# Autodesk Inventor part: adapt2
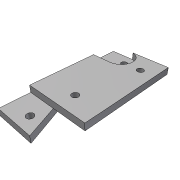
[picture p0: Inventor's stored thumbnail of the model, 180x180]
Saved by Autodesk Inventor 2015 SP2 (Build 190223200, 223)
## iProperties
Created: 2016-02
Part Number: adapt2
Material: S235JR (E24-2)
Document SubType Name: Modeling
Designer: BreysseC
Density: 7.85 g/cm^3
Appearance: Acier
Author: BreysseC
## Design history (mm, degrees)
sketch "Esquisse3"
  geometry: L1 (-26.5, 55)-(26.5, 55); L2 (26.5, 55)-(26.5, -55); L3 (26.5, -55)-(-26.5, -55); L4 (-26.5, -55)-(-26.5, 55); L5 (-37.1, 0)-(37.1, 0) reference; L6 (0, -77)-(0, 77) reference; 3 further points
  constraints: 8 end point, 2 midpoint, 2 parallel, 2 point on line, 1 horizontal, 1 perpendicular
  dimensions: "d4" = 53 distance of L2.end L3.end; "d5" = 110 distance of L1.end L2.end
extrude "Extrusion3" new body sketch "Esquisse3" distance "d6" = 12; taper "d7" = 0 deg
sketch "Esquisse4"
  geometry: L1 (-42.251, -30.5)-(41.829, -30.5); L2 (41.829, -30.5)-(41.829, -65.852); L3 (41.829, -65.852)-(-42.251, -65.852); L4 (-42.251, -65.852)-(-42.251, -30.5); L5 (-26.5, -55)-(26.5, -55) reference; L6 (-38.247, 55.5)-(-9.5, 55.5); L7 (3, 43)-(3, 43); L8 (-9.5, 30.5)-(-38.247, 30.5); L9 (-38.247, 30.5)-(-38.247, 55.5); L10 (26.5, 55)-(-26.5, 55) reference; L11 (-26.5, 55)-(-26.5, -55) reference; A1 r 12.5 centre (-9.5, 43) between (3, 43) and (-9.5, 55.5); A2 r 12.5 centre (-9.5, 43) between (-9.5, 30.5) and (3, 43); 1 further point
  constraints: 16 end point, 4 parallel, 4 point on circle, 4 tangent, 2 centre point, 2 horizontal, 2 perpendicular, 1 concentric
  dimensions: "d8" = 24.5 distance between parallel lines of L1 L5; "d9" = 25 distance of L8.end L6.start; "d10" = 24.5 distance between parallel lines of L8 L10; "d11" = 29.5 distance between parallel lines of L11 L7; "d12" = 12.5 radius of A1; "d13" = 17 distance from line of A1.centre L11 (derived)
extrude "Extrusion4" cut sketch "Esquisse4" distance "d14" = 6; taper "d15" = 0 deg
sketch "Esquisse5"
  geometry: L1 (-26.5, 55)-(6, 55) reference; L2 (-26.5, -55)-(26.5, -55) reference; L3 (-26.5, -55)-(-26.5, 55) reference; L4 (8.206, -9.304)-(-6, 55); L5 (7.684, -16.444)-(-7.5, -55); L6 (26.5, -55)-(-26.5, -55) reference; A1 r 12.5 centre (-4, -12) between (7.631, -16.58) and (8.206, -9.304); 1 further point
  constraints: 4 end point, 3 point on line, 2 point on circle, 2 tangent, 1 centre point
  dimensions: "d16" = 25 diameter of A1; "d18" = 20.5 distance from line of L4.end L3; "d19" = 19 distance from line of L5.end L3; "d20" = 22.5 distance from line of A1.centre L3; "d21" = 43 distance from line of L2 A1.centre
extrude "Extrusion5" cut sketch "Esquisse5" distance "d22" = 6; taper "d23" = 0 deg
sketch "Esquisse6"
  geometry: L1 (-26.5, 55)-(-6, 55) reference; L2 (-26.5, 30.5)-(-26.5, 55) reference; L3 (-26.5, 30.5)-(-26.5, -30.5) reference; L4 (26.5, 55)-(-6, 55) reference; 5 further points
  constraints: 1 vertical alignment
  dimensions: "d24" = 10 distance from line of point (-6.5, 45) L1; "d25" = 90 distance of point (-6.5, -45) point (-6.5, 45); "d26" = 20 distance from line of point (-6.5, 45) L2; "d27" = 40.8 distance from line of point (14.3, 37.287) L2; "d28" = 29.86 distance from line of point (3.36, -16.614) L3; "d29" = 17.713 distance from line of point (14.3, 37.287) L4; "d30" = 55 distance of point (3.36, -16.614) point (14.3, 37.287)
hole "Perçage1" sketch "Esquisse6" at (-6.5, 45), (-6.5, -45), (14.3, 37.287), (3.36, -16.614) diameter "d31" = 6; stored, may be unused: countersink angle "d35" = 90 deg, drill point angle "d37" = 118 deg; dims "d32" = 6, "d33" = 4, "d34" = 2, "d36" = 8
node "Solide2"
node "Corps solides"
node "Corps surfaciques"
